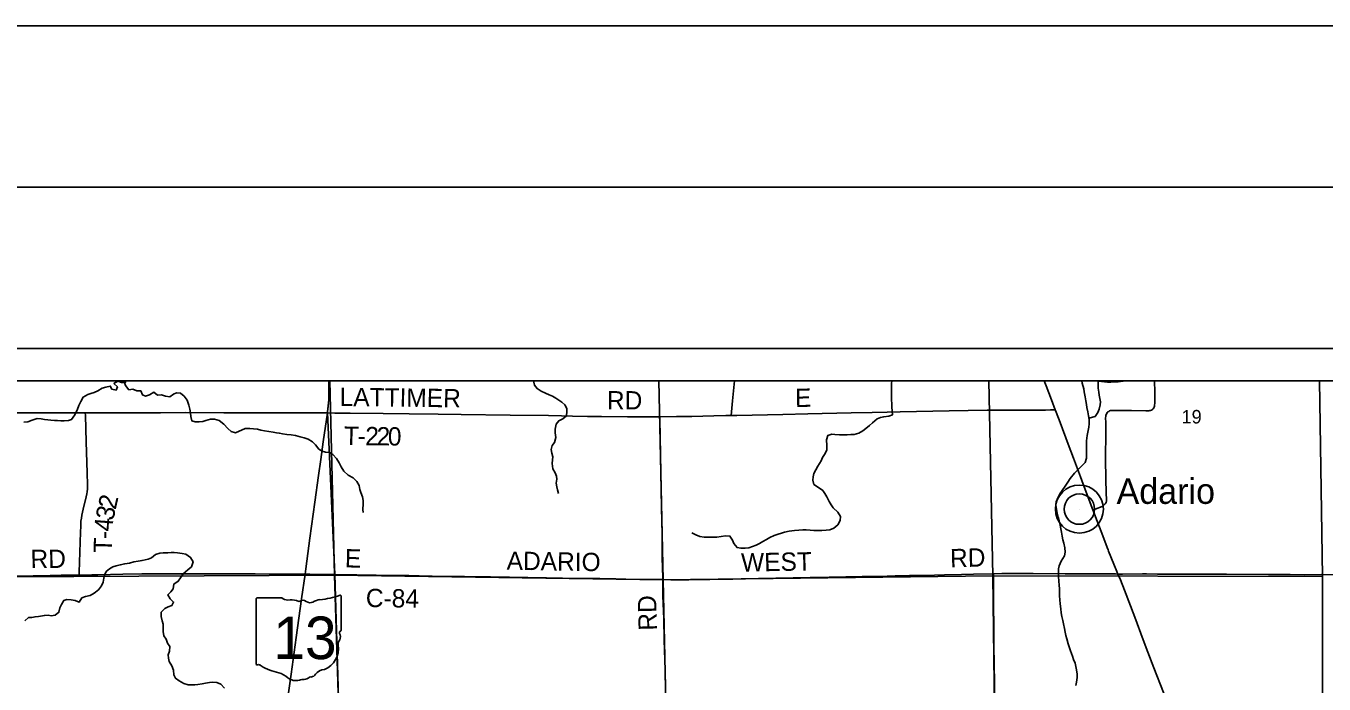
# Model space of a CAD drawing. Extents: x 0 to 34, y 0 to 22.
# Drawn here: x 2.445 to 6.47, y 19.961 to 22 of the extents above; entities that cross this region are included whole.
import ezdxf

# ---------------------------------------------------------------- set-up
doc = ezdxf.new("R2010")
doc.units = 0
for name, color, linetype in [('Default', 7, 'Continuous'), ('GM_X_County_Road', 7, 'Continuous'), ('GM_X_County_Road_Text', 7, 'Continuous'), ('GM_X_Minor_River', 7, 'Continuous'), ('GM_X_Section', 7, 'Continuous'), ('GM_X_Section_Text', 7, 'Continuous'), ('GM_X_State_Location', 7, 'Continuous'), ('GM_X_State_Route', 7, 'Continuous'), ('GM_X_State_Shield', 7, 'Continuous'), ('GM_X_Township_Road', 7, 'Continuous'), ('GM_X_Township_Road_Text', 7, 'Continuous'), ('GM_X_Unincorporated', 7, 'Continuous'), ('GM_X_Unincorporated_Location', 7, 'Continuous'), ('GM_X_Unincorporated_Text', 7, 'Continuous'), ('SH_Border', 7, 'Continuous'), ('SH_Cut_Line', 7, 'Continuous'), ('SH_Data', 7, 'Continuous')]:
    doc.layers.add(name, color=color, linetype=linetype)

msp = doc.modelspace()

# ---------------------------------------------------------------- linework, layer by layer
at = {"layer": 'Default'}
for points in [[(3.4185, 19.7774), (3.4027, 20.3001), (3.3797, 20.8016), (3.3801, 20.8043), (3.3823, 20.8228), (3.3839, 20.8413), (3.3847, 20.8568), (3.3848, 20.8754), (3.3847, 20.9), (2.1, 20.9)], [(7.4609, 20.9), (3.3847, 20.9), (3.3848, 20.8754), (3.3847, 20.8568), (3.3839, 20.8413), (3.3823, 20.8228), (3.3801, 20.8043), (3.3797, 20.8016), (3.4027, 20.3001), (3.4185, 19.7774)]]:
    msp.add_lwpolyline(points, dxfattribs=at)
for points in [[(3.3877, 20.9), (2.3791, 20.9), (2.3914, 20.2927), (3.4017, 20.2979)], [(4.4077, 20.9), (3.3877, 20.9), (3.4017, 20.2979), (4.4204, 20.2835)], [(5.4308, 20.9), (4.4077, 20.9), (4.4204, 20.2835), (5.4429, 20.296)], [(6.4558, 20.9), (5.4308, 20.9), (5.4429, 20.296), (6.4651, 20.2933)]]:
    msp.add_lwpolyline(points, close=True, dxfattribs=at)
at = {"layer": 'GM_X_County_Road'}
for points in [[(5.6364, 20.8106), (5.625, 20.8409), (5.6081, 20.8844), (5.6022, 20.9)], [(5.7531, 20.5001), (5.7231, 20.5795), (5.7144, 20.6023), (5.6927, 20.6606), (5.676, 20.7041), (5.6515, 20.7712), (5.6392, 20.8031), (5.6364, 20.8106)], [(5.8306, 20.3012), (5.8272, 20.309), (5.8177, 20.332), (5.8015, 20.3725), (5.8001, 20.3764), (5.7972, 20.3841), (5.7809, 20.4277), (5.7644, 20.4703), (5.7568, 20.4905), (5.7531, 20.5001)], [(2.1, 20.2953), (2.108, 20.2953), (2.1393, 20.2955), (2.1809, 20.2949), (2.196, 20.2946), (2.2153, 20.2949), (2.2402, 20.295), (2.2701, 20.2949), (2.3054, 20.2945), (2.3272, 20.2947), (2.3398, 20.2948), (2.3615, 20.2951), (2.4019, 20.2953), (2.4672, 20.2962), (2.5201, 20.2973), (2.5543, 20.2981), (2.5847, 20.2979), (2.6105, 20.2983)], [(2.6105, 20.2983), (2.6493, 20.2989), (2.668, 20.2994), (2.7456, 20.3011), (2.8047, 20.3019), (2.9446, 20.3023), (3.0939, 20.3021), (3.156, 20.3018), (3.2586, 20.3012), (3.3021, 20.3009), (3.3107, 20.3009)], [(3.3107, 20.3009), (3.3254, 20.3009), (3.3938, 20.2997), (3.403, 20.2995), (3.4039, 20.2995)], [(3.4039, 20.2995), (3.4715, 20.2986), (3.592, 20.2971), (3.6019, 20.2967), (3.6326, 20.2965), (3.6639, 20.2961), (3.7043, 20.2952), (3.7819, 20.2942), (3.7889, 20.2939), (3.8048, 20.2937), (3.8419, 20.293), (3.8607, 20.2928), (3.8853, 20.2924), (3.9442, 20.2913), (4.0592, 20.2897), (4.109, 20.2888), (4.224, 20.2871), (4.2737, 20.2865), (4.3048, 20.2859), (4.4194, 20.2841)], [(4.4194, 20.2841), (4.4445, 20.2836), (4.4818, 20.2834), (4.5004, 20.2832), (4.5657, 20.2841), (4.637, 20.2855), (4.6622, 20.2861), (4.7704, 20.2883), (4.8765, 20.2902), (4.9359, 20.2915), (5.0378, 20.2933), (5.1157, 20.2946), (5.1406, 20.2955), (5.1747, 20.2959), (5.1841, 20.2964), (5.2306, 20.2973), (5.2927, 20.2987), (5.3456, 20.3), (5.3828, 20.3013), (5.4448, 20.3023)], [(5.4448, 20.3023), (5.4713, 20.3026), (5.5089, 20.3028), (5.5683, 20.3028), (5.6677, 20.3017), (5.7698, 20.3016), (5.8012, 20.3017), (5.8234, 20.3017), (5.8306, 20.3012)], [(5.8306, 20.3012), (5.8449, 20.301), (5.907, 20.3019), (5.9194, 20.3017), (5.9537, 20.3015), (6.0465, 20.3008), (6.1018, 20.3009), (6.167, 20.3009), (6.2976, 20.3001), (6.3411, 20.3001), (6.3639, 20.2998), (6.3649, 20.2998)], [(6.2126, 19.2872), (6.2113, 19.2901), (6.2022, 19.3132), (6.1758, 19.3829), (6.1551, 19.4382), (6.1301, 19.5051), (6.1108, 19.5577), (6.0947, 19.6013), (6.0841, 19.6304), (6.0427, 19.7443), (6.0297, 19.7793), (6.0102, 19.8317), (5.9885, 19.8895), (5.9716, 19.9341), (5.9425, 20.0105), (5.9236, 20.0598), (5.9093, 20.0976), (5.883, 20.1674), (5.851, 20.2516), (5.8383, 20.2834), (5.8306, 20.3012)], [(6.3649, 20.2998), (6.4094, 20.2993), (6.4623, 20.2995), (6.4996, 20.2991), (6.6053, 20.2987), (6.6768, 20.2982), (6.7117, 20.2982)]]:
    msp.add_lwpolyline(points, dxfattribs=at)
at = {"layer": 'GM_X_Minor_River'}
for points in [[(2.6054, 20.8124), (2.6097, 20.8233), (2.6151, 20.8362), (2.6229, 20.8498), (2.637, 20.8576), (2.6465, 20.8613), (2.6564, 20.8642), (2.6686, 20.8693), (2.6813, 20.8779), (2.6927, 20.8801), (2.7068, 20.8841), (2.7112, 20.8746), (2.7245, 20.8717), (2.7288, 20.8819), (2.7179, 20.8916), (2.7297, 20.8994), (2.7414, 20.8955), (2.754, 20.8953), (2.7549, 20.9)], [(2.7509, 20.8954), (2.7539, 20.8855), (2.7643, 20.8724), (2.7769, 20.8749), (2.7894, 20.8695), (2.8015, 20.869), (2.8063, 20.8564), (2.8161, 20.8528), (2.8283, 20.8569), (2.8413, 20.8647), (2.8534, 20.8562), (2.8655, 20.8572), (2.878, 20.8525), (2.8909, 20.8505), (2.9024, 20.8587), (2.9123, 20.8631), (2.9241, 20.8622), (2.9361, 20.8526), (2.9447, 20.8404), (2.9506, 20.8251), (2.9531, 20.8129), (2.9553, 20.8011), (2.9567, 20.7897), (2.9595, 20.7764), (2.9701, 20.7733), (2.9823, 20.7731), (2.9933, 20.7741), (3.0028, 20.7771), (3.0177, 20.7811), (3.0298, 20.7813), (3.0438, 20.7777), (3.0585, 20.7662), (3.0716, 20.752), (3.0818, 20.7431), (3.0947, 20.7388), (3.1247, 20.7521)], [(4.0966, 20.5512), (4.0933, 20.5619), (4.091, 20.5714), (4.0896, 20.5835), (4.0908, 20.5953), (4.0897, 20.6048), (4.0856, 20.6154), (4.0792, 20.6276), (4.077, 20.6443), (4.0782, 20.6549), (4.0786, 20.6648), (4.0752, 20.6758), (4.0741, 20.6879), (4.0772, 20.6993), (4.0837, 20.7092), (4.088, 20.7251), (4.0865, 20.7395), (4.0858, 20.7501), (4.0893, 20.7657), (4.097, 20.7766), (4.1095, 20.7826), (4.1209, 20.7921), (4.1225, 20.805), (4.1218, 20.8148), (4.1165, 20.8255), (4.1063, 20.8346), (4.0886, 20.8465), (4.078, 20.8522), (4.067, 20.8568), (4.0564, 20.8615), (4.0428, 20.8687), (4.0299, 20.8764), (4.0216, 20.8867), (4.019, 20.9)], [(5.1297, 20.9), (5.1292, 20.8915), (5.1291, 20.8783), (5.1287, 20.8638), (5.129, 20.8502), (5.129, 20.8407), (5.1297, 20.8297), (5.13, 20.8194), (5.1311, 20.8058), (5.1314, 20.7944), (5.12, 20.7903), (5.1048, 20.7888), (5.0942, 20.7862), (5.0839, 20.7825), (5.0702, 20.7704), (5.0607, 20.7617), (5.0496, 20.7527), (5.0401, 20.7451), (5.0279, 20.7376), (5.0131, 20.7339), (5.0028, 20.7335), (4.9915, 20.7328), (4.9801, 20.7329), (4.9679, 20.7333), (4.9531, 20.7341), (4.9437, 20.7346), (4.9311, 20.7308), (4.9269, 20.7172), (4.9283, 20.6994), (4.9279, 20.6865), (4.9236, 20.6751), (4.9152, 20.663), (4.9102, 20.6524), (4.9003, 20.6357), (4.8942, 20.6248), (4.888, 20.6126), (4.8857, 20.6032), (4.8845, 20.5926), (4.8875, 20.5793), (4.9023, 20.5693), (4.9155, 20.5605), (4.9219, 20.551), (4.9279, 20.5403), (4.9358, 20.5263), (4.9418, 20.5156), (4.9482, 20.5061), (4.9622, 20.4931), (4.9709, 20.4798), (4.9701, 20.4673), (4.9624, 20.454), (4.9502, 20.4431), (4.938, 20.4386), (4.9259, 20.4375), (4.9126, 20.4368), (4.9027, 20.4361), (4.8876, 20.4362), (4.8766, 20.437), (4.8641, 20.4382), (4.8538, 20.4386), (4.8413, 20.4379), (4.8276, 20.4365), (4.8117, 20.4339), (4.7969, 20.4313), (4.7874, 20.4283), (4.7775, 20.4253), (4.7646, 20.4205), (4.7516, 20.4148), (4.741, 20.4084), (4.7299, 20.402), (4.7193, 20.3964), (4.709, 20.3911), (4.6976, 20.3863), (4.6866, 20.3829), (4.6748, 20.3814), (4.6619, 20.3811), (4.6498, 20.3835), (4.6396, 20.3964), (4.6355, 20.4067), (4.6276, 20.4189), (4.6143, 20.4197), (4.6002, 20.4175), (4.5877, 20.416), (4.5725, 20.4157), (4.5619, 20.4161)], [(5.7191, 20.9), (5.7204, 20.8925), (5.7248, 20.8754), (5.7263, 20.8659), (5.7289, 20.8507), (5.7311, 20.8385), (5.733, 20.8271), (5.7348, 20.8176)], [(5.7405, 20.7847), (5.7597, 20.7894), (5.7689, 20.8019), (5.7727, 20.8125), (5.7762, 20.8254), (5.7763, 20.8353), (5.7748, 20.8455), (5.7729, 20.8554), (5.7715, 20.8649), (5.7696, 20.8774), (5.7693, 20.8956), (5.77, 20.9)], [(5.7699, 20.8996), (5.7891, 20.8971), (5.7986, 20.8959), (5.8088, 20.8962), (5.8217, 20.8969), (5.832, 20.8976), (5.8468, 20.8994), (5.8511, 20.9)], [(2.439, 20.7718), (2.4512, 20.7731), (2.4645, 20.7787), (2.4798, 20.7834), (2.4926, 20.7822), (2.5029, 20.7805), (2.5131, 20.7796), (2.5226, 20.7788), (2.534, 20.7775), (2.5435, 20.777), (2.5537, 20.7765), (2.5636, 20.7764), (2.5769, 20.777), (2.5868, 20.7803), (2.5972, 20.795), (2.6054, 20.8124)], [(5.7348, 20.8176), (5.737, 20.804), (5.7396, 20.7914), (5.7411, 20.7808), (5.7414, 20.7667), (5.7402, 20.7565), (5.7383, 20.7466), (5.7359, 20.7307), (5.7332, 20.714), (5.7331, 20.7015), (5.7334, 20.6886), (5.7334, 20.6757), (5.7329, 20.6609), (5.7287, 20.6476), (5.7203, 20.6378), (5.7073, 20.6253), (5.6966, 20.6144), (5.6829, 20.5978), (5.6756, 20.5864), (5.6672, 20.5736), (5.6577, 20.5599), (5.6504, 20.5497), (5.6454, 20.5399), (5.6393, 20.5251), (5.6385, 20.5149), (5.6399, 20.502), (5.6422, 20.4902), (5.6455, 20.4776), (5.6489, 20.4659), (5.6515, 20.4529), (5.6541, 20.4415), (5.6555, 20.4317), (5.6578, 20.4184), (5.66, 20.4077), (5.6626, 20.3975), (5.6659, 20.383), (5.6674, 20.3694), (5.6654, 20.3576), (5.6551, 20.3417), (5.6486, 20.327), (5.647, 20.3175), (5.6466, 20.305), (5.6461, 20.2936), (5.6472, 20.2795), (5.6483, 20.2666), (5.6498, 20.2552), (5.6497, 20.2442), (5.65, 20.2336), (5.6522, 20.2093), (5.6536, 20.1941), (5.6551, 20.1812), (5.6565, 20.1698), (5.6599, 20.1573), (5.6617, 20.147), (5.6651, 20.1329), (5.6669, 20.1216), (5.6695, 20.1113), (5.6721, 20.1003), (5.6762, 20.0855), (5.68, 20.0756), (5.6837, 20.0634), (5.6897, 20.0474), (5.6931, 20.0368), (5.698, 20.025), (5.7006, 20.0147), (5.7024, 20.0049), (5.7039, 19.9916), (5.7042, 19.9809), (5.7022, 19.9662), (5.6999, 19.9563)], [(3.1247, 20.7521), (3.1395, 20.7521), (3.1505, 20.7512), (3.163, 20.75), (3.1737, 20.7477), (3.185, 20.7454), (3.1987, 20.7427), (3.2119, 20.7411), (3.2218, 20.7395), (3.2313, 20.7376), (3.2408, 20.736), (3.2537, 20.734), (3.2673, 20.7325), (3.2813, 20.7305), (3.295, 20.7266), (3.3075, 20.7235), (3.3207, 20.7197), (3.3336, 20.7113), (3.343, 20.7017), (3.3532, 20.6888), (3.3634, 20.6823), (3.374, 20.6796), (3.3866, 20.678), (3.3968, 20.6715), (3.4077, 20.6593), (3.4164, 20.6464), (3.4224, 20.6334), (3.4307, 20.6201), (3.4447, 20.6083), (3.4598, 20.5991), (3.4715, 20.588), (3.4786, 20.5755), (3.4805, 20.5633), (3.4835, 20.5538), (3.4891, 20.5405), (3.4909, 20.5291), (3.4905, 20.5193), (3.4897, 20.5018), (3.4908, 20.4919)], [(4.5619, 20.4161), (4.5479, 20.4158), (4.5346, 20.4174), (4.5217, 20.4228), (4.5096, 20.4293)], [(2.442, 20.1568), (2.4535, 20.1665), (2.4637, 20.1671), (2.4736, 20.1689), (2.4843, 20.1699), (2.5025, 20.1732), (2.5143, 20.1738), (2.5238, 20.1722), (2.5356, 20.1735), (2.5474, 20.1829), (2.5506, 20.1965), (2.5553, 20.2067), (2.5623, 20.2192), (2.5718, 20.2228), (2.5851, 20.2212), (2.598, 20.2199), (2.61, 20.2141), (2.6186, 20.2276), (2.6304, 20.2317), (2.6444, 20.2349), (2.6563, 20.2424), (2.6697, 20.2525), (2.6797, 20.2649), (2.6851, 20.2758), (2.6872, 20.2887), (2.6884, 20.2982), (2.6942, 20.3088), (2.7042, 20.3178), (2.7145, 20.3237), (2.7252, 20.327), (2.7378, 20.3299), (2.7518, 20.3332), (2.7659, 20.3356), (2.78, 20.3389), (2.7929, 20.3414), (2.8051, 20.3439), (2.8146, 20.3457), (2.8245, 20.3479), (2.8341, 20.3516), (2.8467, 20.3617), (2.86, 20.3657), (2.8707, 20.3667), (2.8851, 20.3673), (2.8954, 20.3679), (2.9049, 20.3682), (2.9151, 20.3673), (2.9295, 20.3653), (2.9405, 20.3625), (2.9556, 20.3528), (2.9641, 20.3394), (2.9583, 20.324), (2.9472, 20.3142), (2.933, 20.3022), (2.9241, 20.2898), (2.9175, 20.2789), (2.9041, 20.2703), (2.9017, 20.2559), (2.8944, 20.2461), (2.8848, 20.2367), (2.8919, 20.2241), (2.9031, 20.2145), (2.8977, 20.2035), (2.8859, 20.1999), (2.8763, 20.1947), (2.8648, 20.183), (2.865, 20.1694), (2.8676, 20.1561), (2.8705, 20.1462), (2.8707, 20.1325), (2.8706, 20.123), (2.8731, 20.1104), (2.8795, 20.0997), (2.8846, 20.0875), (2.8913, 20.0764), (2.8904, 20.062), (2.8865, 20.0511), (2.8871, 20.0404), (2.8893, 20.0305)], [(2.8893, 20.0305), (2.8971, 20.0168), (2.9027, 20.0034), (2.9033, 19.989), (2.9085, 19.9787), (2.9205, 19.9706), (2.9345, 19.9624), (2.9477, 19.9581), (2.9587, 19.9576), (2.9686, 19.9582), (2.9785, 19.9596), (2.9914, 19.9614), (3.0021, 19.9632), (3.0146, 19.9653), (3.0245, 19.9663), (3.0366, 19.9651), (3.0491, 19.96), (3.0607, 19.9473)]]:
    msp.add_lwpolyline(points, dxfattribs=at)
at = {"layer": 'GM_X_Section'}
for points in [[(3.4017, 20.2979), (3.4336, 19.2705), (2.4218, 19.2622), (2.3914, 20.2927)], [(4.4204, 20.2835), (4.4424, 19.2777), (3.4336, 19.2705), (3.4017, 20.2979)], [(5.4429, 20.296), (5.4558, 19.2921), (4.4424, 19.2777), (4.4204, 20.2835)], [(6.4651, 20.2933), (6.4658, 19.2822), (5.4558, 19.2921), (5.4429, 20.296)]]:
    msp.add_lwpolyline(points, close=True, dxfattribs=at)
at = {"layer": 'GM_X_State_Route'}
for points in [[(3.3799, 20.801), (3.3803, 20.8037), (3.3826, 20.8222), (3.3842, 20.8408), (3.3849, 20.8562), (3.3851, 20.8749), (3.3849, 20.9)], [(3.2482, 19.8525), (3.2674, 19.991), (3.2831, 20.105), (3.2998, 20.225), (3.3107, 20.3009), (3.313, 20.3173), (3.3257, 20.4128), (3.341, 20.5237), (3.3525, 20.6068), (3.3594, 20.656), (3.3671, 20.7114), (3.3799, 20.801)]]:
    msp.add_lwpolyline(points, dxfattribs=at)
at = {"layer": 'GM_X_State_Shield'}
for p, q in [((3.1586, 20.2238), (3.1586, 20.0237)), ((3.2384, 20.2273), (3.1612, 20.2273)), ((3.4223, 20.1276), (3.4223, 20.2322)), ((3.4223, 20.1276), (3.4223, 20.1276))]:
    msp.add_line(p, q, dxfattribs=at)
for centre, radius, start, end in [((3.1617, 20.2243), 0.00305, 98.1301, 188.1301), ((3.2568, 20.2505), 0.0296, 231.6195, 271.1119), ((3.2667, 20.1149), 0.1064, 80.4867, 94.9883), ((3.2908, 20.2253), 0.00855, 219.7921, 297.1024), ((3.3034, 20.2022), 0.0178, 54.4667, 119.1411), ((3.3263, 20.2339), 0.0214, 233.8562, 294.8282), ((3.364, 20.1662), 0.0563, 97.3462, 120.7689), ((3.3284, 20.5001), 0.2796, 275.8445, 288.9065), ((3.4194, 20.2327), 0.00294, 351.8621, 97.738), ((3.4216, 20.1199), 0.00454, 107.944, 210.337), ((3.4192, 20.1272), 0.00314, 289.6038, 7.7341), ((3.4328, 20.0838), 0.0198, 136.8065, 186.9296), ((3.3927, 20.1066), 0.0273, 340.033, 23.6496), ((3.344, 20.0704), 0.0699, 292.3089, 8.9858), ((3.1617, 20.0233), 0.00308, 171.9584, 258.3066), ((3.1621, 20.0438), 0.0235, 267.339, 280.6039), ((3.167, 20.0122), 0.00848, 29.7484, 93.2717), ((3.274, 20.192), 0.2019, 240.4129, 257.1985), ((3.3735, 19.9675), 0.0383, 94.4031, 142.5768), ((3.2138, 19.9338), 0.0632, 47.1842, 75.836), ((3.2822, 20.0112), 0.0401, 230.7004, 286.2918), ((3.3053, 19.942), 0.0329, 85.6951, 111.2099), ((3.3082, 19.9962), 0.0214, 268.777, 315.5493), ((3.3276, 19.9768), 0.00601, 65.7517, 132.6484), ((3.325, 20.0043), 0.0226, 282.8732, 323.2771)]:
    msp.add_arc(centre, radius, start, end, dxfattribs=at)
at = {"layer": 'GM_X_Township_Road'}
for points in [[(4.6321, 20.7928), (4.6331, 20.8043), (4.6361, 20.8384), (4.6421, 20.9)], [(5.7531, 20.5001), (5.7597, 20.5026), (5.7815, 20.5109), (5.7853, 20.513), (5.7908, 20.5187), (5.7939, 20.5234), (5.7951, 20.5288), (5.7951, 20.5361), (5.7938, 20.5477), (5.792, 20.6528), (5.7921, 20.6838), (5.7922, 20.6879), (5.7932, 20.7124), (5.7928, 20.7717), (5.7927, 20.784), (5.793, 20.7902), (5.7936, 20.7932), (5.7946, 20.7962), (5.7959, 20.799), (5.7976, 20.8016), (5.7997, 20.8038), (5.8023, 20.8056), (5.8051, 20.8069), (5.8081, 20.8078), (5.8111, 20.8083), (5.8173, 20.8086), (5.8733, 20.8081), (5.9168, 20.8074), (5.9261, 20.8076), (5.9292, 20.808), (5.9322, 20.8087), (5.9351, 20.8098), (5.9376, 20.8115), (5.9398, 20.8137), (5.9416, 20.8162), (5.943, 20.819), (5.9439, 20.822), (5.9444, 20.825), (5.9448, 20.8312), (5.9447, 20.8654), (5.9446, 20.9)], [(4.6321, 20.7928), (4.6492, 20.7932), (4.7921, 20.7961), (4.8697, 20.7978), (5.0033, 20.8006), (5.0686, 20.8022), (5.1152, 20.8031), (5.1556, 20.8042), (5.3078, 20.8076), (5.4258, 20.8094), (5.5004, 20.8093), (5.5719, 20.8092), (5.6061, 20.8093), (5.6216, 20.81), (5.6364, 20.8106)], [(2.3849, 20.8013), (2.4124, 20.8014), (2.5957, 20.8009), (2.6291, 20.8009)], [(2.6105, 20.2983), (2.6107, 20.307), (2.6147, 20.4312), (2.6151, 20.4498), (2.6159, 20.4653), (2.6171, 20.4746), (2.6187, 20.4837), (2.6225, 20.502), (2.632, 20.5412), (2.6339, 20.5503), (2.6349, 20.5565), (2.6357, 20.5657), (2.6359, 20.5781), (2.635, 20.6154), (2.632, 20.7116), (2.6294, 20.7923), (2.6291, 20.8009)], [(2.6291, 20.8009), (2.7107, 20.8009), (2.7542, 20.8008), (2.7977, 20.8012), (2.8629, 20.8014), (2.9405, 20.8016), (3.0586, 20.8011), (3.2326, 20.8009), (3.3258, 20.8008), (3.3568, 20.8011), (3.3754, 20.8011), (3.3799, 20.801)], [(3.3799, 20.801), (3.4034, 20.8005), (3.45, 20.7998), (3.5525, 20.7987), (3.6333, 20.7977), (3.7234, 20.7964), (3.7948, 20.7955), (3.947, 20.7941), (4.0651, 20.7924), (4.1054, 20.7914), (4.1396, 20.7909), (4.1862, 20.7901), (4.2297, 20.7899), (4.3105, 20.7891), (4.3664, 20.7885), (4.4104, 20.7888)], [(4.4104, 20.7888), (4.4627, 20.7894), (4.5094, 20.7901), (4.5777, 20.7918), (4.615, 20.7925), (4.6321, 20.7928)], [(4.4194, 20.2841), (4.4195, 20.29), (4.418, 20.3521), (4.4173, 20.4236), (4.4158, 20.5075), (4.4138, 20.6163), (4.4118, 20.7282), (4.4106, 20.781), (4.4104, 20.7888)], [(4.4332, 19.7821), (4.4329, 19.7864), (4.4314, 19.8268), (4.429, 19.8983), (4.428, 19.948), (4.4267, 20.0039), (4.4241, 20.0971), (4.4225, 20.1624), (4.4203, 20.2338), (4.4194, 20.2711), (4.4194, 20.2841)], [(5.4546, 19.294), (5.4543, 19.3063), (5.4545, 19.3498), (5.454, 19.384), (5.4538, 19.412), (5.4528, 19.4617), (5.4492, 19.8287), (5.4491, 19.8827), (5.4487, 19.9138), (5.4486, 19.9387), (5.4479, 19.9728), (5.4474, 20.013), (5.4465, 20.0893), (5.4456, 20.1512), (5.4454, 20.1914), (5.4449, 20.2901), (5.4448, 20.3023)]]:
    msp.add_lwpolyline(points, dxfattribs=at)
at = {"layer": 'GM_X_Unincorporated'}
for radius in [0.0744, 0.0472]:
    msp.add_circle((5.7113, 20.5027), radius, dxfattribs=at)
at = {"layer": 'GM_X_Unincorporated_Location'}
msp.add_line((5.7113, 20.5027), (5.7113, 20.5027), dxfattribs=at)
at = {"layer": 'SH_Border'}
msp.add_lwpolyline([(1.5, 21.5), (33.5, 21.5), (33.5, 0.5), (1.5, 0.5)], close=True, dxfattribs=at)
at = {"layer": 'SH_Cut_Line'}
msp.add_lwpolyline([(0, 0), (34, 0), (34, 22), (0, 22)], close=True, dxfattribs=at)
msp.add_lwpolyline([(7.5053, 17.3084), (7.5051, 18.039), (7.5056, 18.0926), (7.5011, 18.2616), (7.4731, 18.2617), (7.4732, 18.3097), (6.7366, 18.3097), (6.7366, 18.9662), (7.4751, 18.9662), (7.476, 19.2764), (7.4665, 20.2923), (7.4609, 20.9), (2.1, 20.9), (2.1, 14.1)], dxfattribs=at)
at = {"layer": 'SH_Data'}
for p, q in [((2, 21), (9, 21)), ((2.1, 20.9), (8.9, 20.9))]:
    msp.add_line(p, q, dxfattribs=at)

# ---------------------------------------------------------------- texts
at = {"layer": 'GM_X_County_Road_Text'}
for s, height, rotation, p in [('RD', 0.05682, 0.4981, (2.4596, 20.3196)), ('E', 0.0568, 358.8773, (3.4336, 20.3221)), ('ADARIO', 0.05682, 359.1164, (3.9353, 20.3146)), ('WEST', 0.05682, 1.0055, (4.6628, 20.3088)), ('RD', 0.05682, 1.4808, (5.311, 20.3221)), ('C-84', 0.05682, 359.1295, (3.4987, 20.1993))]:
    msp.add_text(s, height=height, rotation=rotation, dxfattribs=at).set_placement(p)
at = {"layer": 'GM_X_Section_Text'}
msp.add_text('19', height=0.04186, rotation=0, dxfattribs=at).set_placement((6.0281, 20.7681))
at = {"layer": 'GM_X_State_Location'}
msp.add_text('13', height=0.000189, rotation=0, dxfattribs=at).set_placement((3.2398, 20.0967))
for s in ['s', 'r']:
    msp.add_text(s, height=0.000189, dxfattribs=at).set_placement((3.2875, 20.1105))
at = {"layer": 'GM_X_State_Shield'}
msp.add_text('13', height=0.13184, dxfattribs=at).set_placement((3.2123, 20.0378))
at = {"layer": 'GM_X_Township_Road_Text'}
for s, height, rotation, p in [('LATTIMER', 0.05682, 359.3227, (3.4176, 20.8222)), ('RD', 0.05682, 0, (4.2465, 20.8114)), ('E', 0.0568, 1.1227, (4.8302, 20.8189)), ('T', 0.0568, 358.4999, (3.4303, 20.7021)), ('2', 0.0568, 359.3271, (3.497, 20.7007)), ('2', 0.0568, 359.3806, (3.5321, 20.7002)), ('0', 0.0568, 359.385, (3.5671, 20.6999)), ('-', 0.0568, 359.2113, (3.4736, 20.701)), ('2', 0.0568, 77.1957, (2.7232, 20.4988)), ('3', 0.0568, 77.6388, (2.7157, 20.4647)), ('4', 0.0568, 85.7653, (2.7134, 20.4319)), ('T', 0.0568, 88.5984, (2.7117, 20.3668)), ('-', 0.0568, 88.2513, (2.7128, 20.4092)), ('RD', 0.05682, 91.4806, (4.4016, 20.1267))]:
    msp.add_text(s, height=height, rotation=rotation, dxfattribs=at).set_placement(p)
at = {"layer": 'GM_X_Unincorporated_Text'}
msp.add_text('Adario', height=0.07898, rotation=0, dxfattribs=at).set_placement((5.8265, 20.5189))

doc.saveas('drawing.dxf')
